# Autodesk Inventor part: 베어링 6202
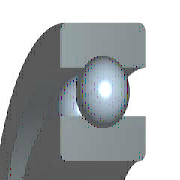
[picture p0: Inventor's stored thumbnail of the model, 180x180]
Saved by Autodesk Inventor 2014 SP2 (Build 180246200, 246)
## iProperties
IsCustomPart: 1
Created: 2015-12
Part Number: 베어링 6202
Material: 강철, 연강
Description: 깊은 그루브 볼 베어링
Document SubType Name: Modeling
Standard: KS B 2023
Designer: mdu
Standards Organization: KS
Language: ko-KR
Size Designation: 6202 - 15 x 35 x 11
Categories: <MemberInstance><Categories><Category DisplayName="샤프트 부품" InternalName="7f7aeb1f-a693-4053-b835-cee3144e0d98" Mnemonic="SHFT"><Category DisplayName="베어링" Inter
Density: 7.86 g/cm^3
Mass: 45.8725 g
Surface Area: 51.5584 cm^2
Volume: 5.83619 cm^3
Appearance: 노란색
Author: mdu
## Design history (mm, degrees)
sketch "스케치" dims "d0" = 5.2 (= -0.26 x WD + 0.26 x BD)
  geometry: L1 (2.9, 12.5)-(8.1, 12.5); L2 (5.5, 12.5)-(5.5, 9.9); L3 (5.5, 12.5)-(5.5, 15.1); L4 (3.568, 10.76)-(0, 10.76); L5 (0, 7.5)-(11, 7.5); L6 (3.568, 14.24)-(0, 14.24); L7 (0, 17.5)-(11, 17.5); L8 (11, 7.5)-(11, 10.76); L9 (7.432, 10.76)-(11, 10.76); L10 (7.432, 14.24)-(11, 14.24); L11 (11, 17.5)-(11, 14.24); L12 (-1.4, 0)-(8.4, 0) reference; L13 (0, -0.3)-(0, 5.3) reference
  constraints: 22 end point, 4 point on line, 2 collinear, 2 perpendicular, 2 symmetric about line, 1 midpoint, 1 parallel, 14 other
  dimensions: "d9" = 15 diameter of L5 L12 (= WD); "d11" = 35 diameter of L7 L12 (= BD); "d12" = 11 distance between parallel lines of L8 L13 (= KB); "d13" = 21.52 diameter of L9 L12 (= 0.326 x BD + 0.674 x WD)
revolve "본체" stored, may be unused: angle "d6" = 90 deg
revolve "볼" stored, may be unused: angle "d7" = 90 deg
pattern_circular "IDS_ARRAYBALL[SIMPL:T]" dims angle "d3" = 360 deg
body "Solid1"
fillet "모깎기1" dims "d1" = 0.6 (= KRS)
other parameters: "WD" = 15 [user parameter; used in 5 equation terms], "BD" = 35 [user parameter; used in 5 equation terms], "KB" = 11 [user parameter; used in 1 equation term], "KRS" = 0.6 [user parameter; used in 1 equation term], "d4" = 0, "d5" = 0, "d8" = 0, "d14" = 0, "d15" = 0, "BBA" = 0 [user parameter], "BC0" = 3750000 [user parameter], "BC" = 7800000 [user parameter], "BR" = 17.5 (= 0.5 x BD) [user parameter], "WR" = 7.5 (= 0.5 x WD) [user parameter]
